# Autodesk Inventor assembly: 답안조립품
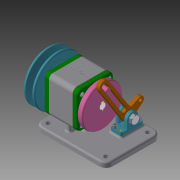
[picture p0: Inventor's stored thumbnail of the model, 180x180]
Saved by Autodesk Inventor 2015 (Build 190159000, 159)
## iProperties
Created: 2020-11
Part Number: 답안조립품
Document SubType Name: Assembly
Designer: 101258642
Mass: 1532.4 g
Surface Area: 1486.39 cm^2
Volume: 469.454 cm^3
Density: 3.26422 g/cm^3
Author: 101258642
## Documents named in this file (19)
- C:\Users\101258642\Desktop\601106V1007\답안조립품.iam
- C:\Users\101258642\Desktop\601106V1007\본체.ipt
- C:\Users\101258642\Desktop\601106V1007\V-벨트풀리.ipt
- C:\Users\101258642\Desktop\601106V1007\너트 M8.ipt
- C:\Users\101258642\Desktop\601106V1007\너트 M10x1.ipt
- C:\Users\101258642\Desktop\601106V1007\돌림판.ipt
- C:\Users\101258642\Desktop\601106V1007\멈춤나사 M3x5.ipt
- C:\Users\101258642\Desktop\601106V1007\베어링 6004.ipt
- C:\Users\101258642\Desktop\601106V1007\볼트 M4.ipt
- C:\Users\101258642\Desktop\601106V1007\오일 실 17 30 5.ipt
- C:\Users\101258642\Desktop\601106V1007\와셔 8x15.5.ipt
- C:\Users\101258642\Desktop\601106V1007\축.ipt
- C:\Users\101258642\Desktop\601106V1007\커버.ipt
- C:\Users\101258642\Desktop\601106V1007\크랭크.ipt
- C:\Users\101258642\Desktop\601106V1007\키 4 x 4 x 8.ipt
- C:\Users\101258642\Desktop\601106V1007\키 5 x 5 x 12.ipt
- C:\Users\101258642\Desktop\601106V1007\핀 3 x 8.ipt
- C:\Users\101258642\Desktop\601106V1007\힌지 축.ipt
- C:\Users\101258642\Desktop\601106V1007\힌지.ipt
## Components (3 placed, 2 different names)
1. V-벨트풀리:1
2. 핀 3 x 8:1 — 플러쉬:2
3. 핀 3 x 8:2 — 플러쉬:3
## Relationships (2: Flush 2)
- 플러쉬:2 [Flush]: 핀 3 x 8:1
- 플러쉬:3 [Flush]: 핀 3 x 8:2
